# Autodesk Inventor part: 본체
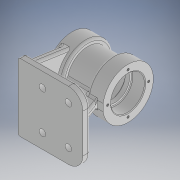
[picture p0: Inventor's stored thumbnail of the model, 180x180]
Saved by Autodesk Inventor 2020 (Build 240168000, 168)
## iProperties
Created: 2024-02
Part Number: 본체
Material: 일반
Document SubType Name: Modeling
Designer: oem
Density: 1 g/cm^3
Appearance: 기본값
Author: oem
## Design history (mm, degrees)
sketch "스케치1"
  geometry: C1 r 28.5 at (0, 0); 1 further point
  constraints: 1 centre point, 1 coincident
  dimensions: "d0" = 57 diameter of C1
extrude "돌출1" new body sketch "스케치1" distance "d1" = 78; taper "d2" = 0 deg
node "작업 평면1"
sketch "스케치4"
  geometry: L1 (78, -28.5)-(78, 28.5) reference; L2 (0, -28.5)-(0, 28.5) reference; L3 (0, 0)-(78, 0); L4 (5, -47)-(95, -47); L5 (95, -47)-(95, 47); L6 (95, 47)-(5, 47); L7 (5, 47)-(5, -47)
  constraints: 10 end point, 2 parallel, 1 horizontal, 1 midpoint, 1 perpendicular
  dimensions: "d22" = 5 distance between parallel lines of L7 L2; "d23" = 90 distance between parallel lines of L5 L7; "d24" = 94 distance between parallel lines of L6 L4; "d25" = 47 distance between parallel lines of L3 L4
extrude "돌출2" join sketch "스케치4" distance "d26" = 10; taper "d27" = 0 deg
sketch "스케치5"
  geometry: L1 (-10, 0)-(-10, 94) reference; L2 (-10, 8)-(-84.109, 18.798); L3 (-10, 94)-(-10, 0) reference; L4 (-10, 86)-(-84.109, 75.202); A1 r 28.5 centre (-80, 47) between (-84.109, 75.202) and (-84.109, 18.798) reference; 2 further points
  constraints: 4 end point, 2 point on circle, 2 point on line, 2 tangent
  dimensions: "d28" = 8 distance of L2.start L1.start; "d29" = 8 distance of L4.start L1.end
extrude "돌출3" join sketch "스케치5" distance "d30" = 10; taper "d31" = 0 deg
sketch "스케치7"
  geometry: L1 (-5, 47)-(-5, -47) reference; C1 r 10 at (-39, -27); C2 r 10 at (-75, -27); C3 r 10 at (-75, 27); C4 r 10 at (-39, 27); 1 further point
  constraints: 4 centre point
  dimensions: "d38" = 20 diameter of C1; "d39" = 20 diameter of C2; "d40" = 20 diameter of C3; "d41" = 20 diameter of C4; "d42" = 34 distance from line of C1.centre L1; "d43" = 34 distance from line of L1 C4.centre; "d44" = 36 distance of C2.centre C1.centre; "d45" = 36 distance of C3.centre C4.centre; "d46" = 27 vertical distance of point (0, 0) C1.centre; "d47" = 27 vertical distance of point (0, 0) C4.centre; "d48" = 27 vertical distance of point (0, 0) C2.centre; "d49" = 27 vertical distance of point (0, 0) C3.centre
extrude "돌출5" join sketch "스케치7" distance "d50" = 3; taper "d51" = 0 deg
sketch "스케치8"
  geometry: C1 r 10 at (0, 0) reference; C2 r 4.5 at (0, 0); C3 r 10 at (36, 0) reference; C4 r 4.5 at (36, 0); C5 r 10 at (36, -54) reference; C6 r 4.5 at (36, -54); C7 r 10 at (0, -54) reference; C8 r 4.5 at (0, -54); 1 further point
  constraints: 4 centre point, 4 coincident
  dimensions: "d52" = 9 diameter of C2; "d53" = 9 diameter of C4; "d54" = 9 diameter of C6; "d55" = 9 diameter of C8
extrude "돌출6" cut sketch "스케치8" extent not by distance; stored distance "d56" = 89.271; taper "d57" = 0 deg
sketch "스케치12"
  geometry: C1 r 28.5 at (0, 0) reference; C2 r 35 at (0, 0)
  constraints: 1 centre point, 1 coincident
  dimensions: "d82" = 70 diameter of C2
extrude "돌출9" join sketch "스케치12" distance "d83" = 22; taper "d84" = 0 deg
sketch "스케치14"
  geometry: C1 r 28.5 at (0, 0) reference; C2 r 35 at (0, 0)
  constraints: 1 centre point, 1 coincident
  dimensions: "d88" = 70 diameter of C2
extrude "돌출11" join sketch "스케치14" distance "d89" = 22; taper "d90" = 0 deg
node "작업 평면2"
node "작업 평면3"
sketch "스케치18"
  geometry: L1 (0, 35)-(0, -35) reference; C1 r 6 at (39, 0); 1 further point
  constraints: 1 centre point
  dimensions: "d107" = 12 diameter of C1; "d108" = 39 distance from line of C1.centre L1
extrude "돌출14" join sketch "스케치18" stored distance "d109" = 3; taper "d110" = 0 deg
sketch "스케치19"
  geometry: C1 r 6 at (0, 0) reference; C2 r 3.5 at (0, 0); 1 further point
  constraints: 1 centre point, 1 coincident
  dimensions: "d111" = 7 diameter of C2
extrude "돌출15" cut sketch "스케치19" distance "d112" = 2; taper "d113" = 0 deg
sketch "스케치17"
  geometry: L1 (-78, 35)-(-78, -35) reference; L2 (-18, 0)-(-18, -22.5); L3 (-17, -23.5)-(0, -23.5); L4 (0, -23.5)-(0, 0); L5 (-18, 0)-(-24, 0); L6 (-24, 0)-(-24, -20); L7 (-24, -20)-(-18, -20); L8 (-18, -20)-(-18, 0); L9 (-24, 0)-(-54, 0); L10 (-54, 0)-(-54, -20.5); L11 (-51, -23.5)-(-27, -23.5); L12 (-24, -20.5)-(-24, 0); L13 (-54, 0)-(-60, 0); L14 (-60, 0)-(-60, -20); L15 (-60, -20)-(-54, -20); L16 (-54, -20)-(-54, 0); L17 (-60, 0)-(-78, 0); L18 (-78, 0)-(-78, -23.5); L19 (-78, -23.5)-(-61, -23.5); L20 (-60, -22.5)-(-60, 0); L21 (0, 0)-(-18, 0); L22 (0, -35)-(0, 35) reference; A1 r 1 centre (-17, -22.5) between (-18, -22.5) and (-17, -23.5); A2 r 1 centre (-61, -22.5) between (-61, -23.5) and (-60, -22.5); A3 r 3 centre (-27, -20.5) between (-27, -23.5) and (-24, -20.5); A4 r 3 centre (-51, -20.5) between (-54, -20.5) and (-51, -23.5); 9 further points
  constraints: 40 end point, 12 point on line, 9 parallel, 8 point on circle, 8 tangent, 5 perpendicular, 4 centre point, 4 horizontal, 2 equal radius
  dimensions: "d99" = 18 distance of L3.end point (-18, -23.5); "d100" = 30 distance of point (-24, -23.5) point (-54, -23.5); "d101" = 18 distance of L18.end point (-60, -23.5); "d102" = 6 distance between parallel lines of L6 L8; "d103" = 47 diameter of L3 L21; "d104" = 40 diameter of L7 L5; "d129" = 1 radius of A1; "d130" = 3 radius of A3
revolve "회전1" sketch "스케치17" stored, may be unused: angle "d105" = 90 deg
sketch "스케치20"
  geometry: C1 r 6 at (0, 0) reference; 2 further points
  constraints: 1 coincident
hole "구멍4" sketch "스케치20" at (0, 0) diameter "d114" = 4.917; stored, may be unused: countersink angle "d118" = 90 deg, drill point angle "d120" = 118 deg; dims "d115" = 12, "d116" = 4, "d117" = 2, "d119" = 17.1
chamfer "모따기1" distance "d131" = 1; stored, may be unused: second distance "d132" = 2, angle "d133" = 45 deg
fillet "모깎기15" dims "d139" = 3
fillet "모깎기16" dims "d140" = 3
fillet "모깎기17" dims "d141" = 3
fillet "모깎기18" dims "d142" = 3
fillet "모깎기19" dims "d143" = 3
fillet "모깎기22" dims "d154" = 20
fillet "모깎기23" dims "d155" = 3
sketch "스케치27"
  geometry: L1 (-5, 44)-(-5, -44) reference; L2 (-5, -5)-(-83, -5); L3 (-83, -5)-(-83, 5); L4 (-83, 5)-(-5, 5); L5 (-5, 5)-(-5, -5); L6 (-95, 27)-(-95, -27) reference; 2 further points
  constraints: 8 end point, 2 parallel, 1 horizontal, 1 perpendicular, 1 point on line
  dimensions: "d175" = 12 distance between parallel lines of L3 L6; "d176" = 5 distance from line of point (0, 0) L2; "d177" = 10 distance between parallel lines of L4 L2
extrude "돌출20" join sketch "스케치27" stored distance "d178" = 10; taper "d179" = 0 deg
sketch "스케치28"
  geometry: L1 (63, 35.359)-(63, 41.942) reference; L2 (44, 35.359)-(63, 35.359) reference; L3 (68, 0)-(0, 0) reference; L4 (68, 0)-(68, 41.942) reference; L5 (63, 41.942)-(68, 41.942) reference; L6 (68, 0)-(55.13, 35.359); 1 further point
  constraints: 2 end point, 1 point on line
  dimensions: "d180" = 70 deg angle of L3 L6
extrude "돌출21" cut sketch "스케치28" distance "d181" = 10; taper "d182" = 0 deg
fillet "모깎기24" dims "d183" = 3
fillet "모깎기25" dims "d184" = 3
fillet "모깎기26" dims "d185" = 3
fillet "모깎기27" dims "d186" = 3
fillet "모깎기28" dims "d187" = 3
sketch "스케치29" dims "d188" = 57
  geometry: C1 r 20.5 at (0, 0) reference; 2 further points
  constraints: 1 coincident, 1 horizontal alignment, 2 other
hole "구멍7" sketch "스케치29" at (-28.5, 0) diameter "d189" = 3.242; stored, may be unused: countersink angle "d193" = 90 deg, drill point angle "d195" = 118 deg; dims "d190" = 8, "d191" = 4, "d192" = 2, "d194" = 10
sketch "스케치30"
  geometry: C1 r 1.621 at (28.5, 0) reference; C2 r 1.621 at (0, 28.5) reference; C3 r 1.621 at (-28.5, 0) reference; C4 r 1.621 at (0, -28.5) reference
hole "구멍8" sketch "스케치30" at (0, -28.5), (28.5, 0), (0, 28.5), (-28.5, 0) diameter "d199" = 3.242; stored, may be unused: countersink angle "d203" = 90 deg, drill point angle "d205" = 118 deg; dims "d200" = 8, "d201" = 4, "d202" = 2, "d204" = 10
sketch "스케치31"
  geometry: L1 (57.556, -20.362)-(57.556, 21.117); L2 (57.556, 21.117)-(63.56, 21.117); L3 (63.56, 21.117)-(63.56, -20.362); L4 (63.56, -20.362)-(57.556, -20.362)
  constraints: 2 other
feature "엠보싱1" sketch "스케치31" dims "d0" = 57, "d206" = 0.5, "d207" = 0
fillet "모깎기29" dims "d208" = 3
node "솔리드1"
pattern_circular "원형 패턴3" dims angle "d197" = 360 deg
node "투영된 루프1"
node "투영된 루프2"
feature "A9D066F2-1C7D-4E18-AEED-F7BC21143FA4" dims "d189" = 3.242, "d190" = 8, "d191" = 4, "d192" = 2, "d193" = 90 deg, "d194" = 10, "d195" = 118 deg
other parameters: "d91" = -25.5, "d106" = -31.5
